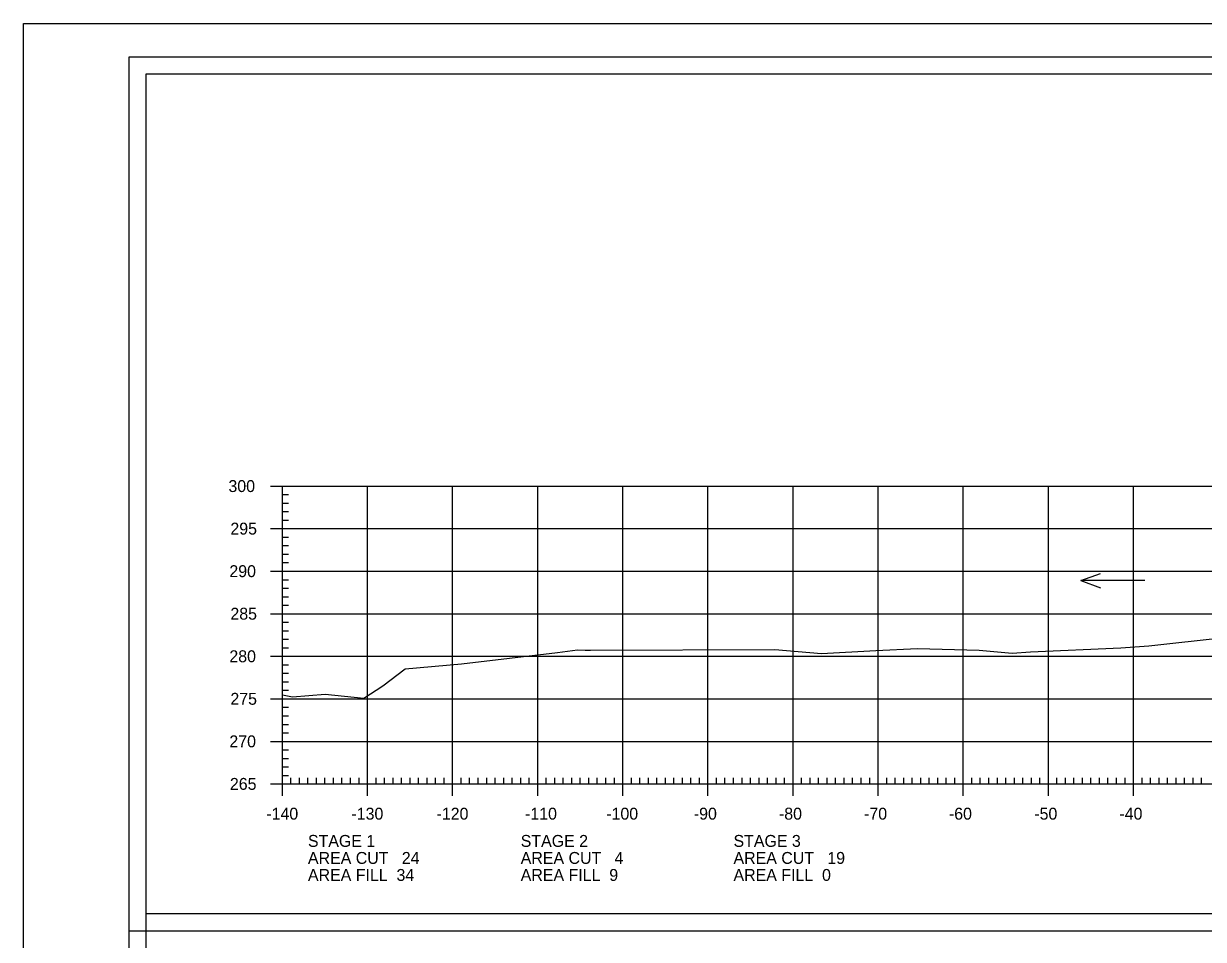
# Model space of a CAD drawing. Extents: x 1368713 to 1370673, y 380279 to 380950.
# Drawn here: x 1370339.2 to 1370477.8, y 380416.1 to 380523.8 of the extents above; entities that cross this region are included whole.
import ezdxf

# ---------------------------------------------------------------- set-up
doc = ezdxf.new("R2010")
doc.units = 0
for name, color, linetype in [('R_Axis', 7, 'Continuous'), ('R_Axis Annot', 7, 'Continuous'), ('R_Border', 7, 'Continuous'), ('R_Border Plan-Plan', 7, 'Continuous'), ('R_Exist Surface', 7, 'Continuous'), ('R_Grid', 7, 'Continuous'), ('R_No Plot', 7, 'Continuous'), ('R_Water Annot', 7, 'Continuous')]:
    doc.layers.add(name, color=color, linetype=linetype)

msp = doc.modelspace()

# ---------------------------------------------------------------- linework, layer by layer
at = {"layer": 'R_Axis'}
for p, q in [((1370368.23, 380469.42), (1370371.03, 380469.42)), ((1370369.63, 380434.42), (1370369.63, 380469.42)), ((1370369.63, 380468.42), (1370370.33, 380468.42)), ((1370369.63, 380467.42), (1370370.33, 380467.42)), ((1370369.63, 380466.42), (1370370.33, 380466.42)), ((1370369.63, 380465.42), (1370370.33, 380465.42)), ((1370368.23, 380464.42), (1370371.03, 380464.42)), ((1370369.63, 380463.42), (1370370.33, 380463.42)), ((1370369.63, 380462.42), (1370370.33, 380462.42)), ((1370369.63, 380461.42), (1370370.33, 380461.42)), ((1370368.23, 380459.42), (1370371.03, 380459.42)), ((1370369.63, 380460.42), (1370370.33, 380460.42)), ((1370369.63, 380458.42), (1370370.33, 380458.42)), ((1370369.63, 380457.42), (1370370.33, 380457.42)), ((1370369.63, 380456.42), (1370370.33, 380456.42)), ((1370369.63, 380455.42), (1370370.33, 380455.42)), ((1370368.23, 380454.42), (1370371.03, 380454.42)), ((1370369.63, 380453.42), (1370370.33, 380453.42)), ((1370369.63, 380452.42), (1370370.33, 380452.42)), ((1370369.63, 380451.42), (1370370.33, 380451.42)), ((1370369.63, 380450.42), (1370370.33, 380450.42)), ((1370368.23, 380449.42), (1370371.03, 380449.42)), ((1370369.63, 380448.42), (1370370.33, 380448.42)), ((1370369.63, 380447.42), (1370370.33, 380447.42)), ((1370369.63, 380446.42), (1370370.33, 380446.42)), ((1370368.23, 380444.42), (1370371.03, 380444.42)), ((1370369.63, 380445.42), (1370370.33, 380445.42)), ((1370369.63, 380443.42), (1370370.33, 380443.42)), ((1370369.63, 380442.42), (1370370.33, 380442.42)), ((1370369.63, 380441.42), (1370370.33, 380441.42)), ((1370369.63, 380440.42), (1370370.33, 380440.42)), ((1370368.23, 380439.42), (1370371.03, 380439.42)), ((1370369.63, 380438.42), (1370370.33, 380438.42)), ((1370369.63, 380437.42), (1370370.33, 380437.42)), ((1370369.63, 380436.42), (1370370.33, 380436.42)), ((1370369.63, 380433.02), (1370369.63, 380435.82)), ((1370379.63, 380433.02), (1370379.63, 380435.82)), ((1370389.63, 380433.02), (1370389.63, 380435.82)), ((1370399.63, 380433.02), (1370399.63, 380435.82)), ((1370409.63, 380433.02), (1370409.63, 380435.82)), ((1370419.63, 380433.02), (1370419.63, 380435.82)), ((1370429.63, 380433.02), (1370429.63, 380435.82)), ((1370439.63, 380433.02), (1370439.63, 380435.82)), ((1370449.63, 380433.02), (1370449.63, 380435.82)), ((1370459.63, 380433.02), (1370459.63, 380435.82)), ((1370469.63, 380433.02), (1370469.63, 380435.82)), ((1370369.63, 380435.42), (1370370.33, 380435.42)), ((1370370.63, 380434.42), (1370370.63, 380435.12)), ((1370371.63, 380434.42), (1370371.63, 380435.12)), ((1370372.63, 380434.42), (1370372.63, 380435.12)), ((1370373.63, 380434.42), (1370373.63, 380435.12)), ((1370374.63, 380434.42), (1370374.63, 380435.12)), ((1370375.63, 380434.42), (1370375.63, 380435.12)), ((1370376.63, 380434.42), (1370376.63, 380435.12)), ((1370377.63, 380434.42), (1370377.63, 380435.12)), ((1370378.63, 380434.42), (1370378.63, 380435.12)), ((1370380.63, 380434.42), (1370380.63, 380435.12)), ((1370381.63, 380434.42), (1370381.63, 380435.12)), ((1370382.63, 380434.42), (1370382.63, 380435.12)), ((1370383.63, 380434.42), (1370383.63, 380435.12)), ((1370384.63, 380434.42), (1370384.63, 380435.12)), ((1370385.63, 380434.42), (1370385.63, 380435.12)), ((1370386.63, 380434.42), (1370386.63, 380435.12)), ((1370387.63, 380434.42), (1370387.63, 380435.12)), ((1370388.63, 380434.42), (1370388.63, 380435.12)), ((1370390.63, 380434.42), (1370390.63, 380435.12)), ((1370391.63, 380434.42), (1370391.63, 380435.12)), ((1370392.63, 380434.42), (1370392.63, 380435.12)), ((1370393.63, 380434.42), (1370393.63, 380435.12)), ((1370394.63, 380434.42), (1370394.63, 380435.12)), ((1370395.63, 380434.42), (1370395.63, 380435.12)), ((1370396.63, 380434.42), (1370396.63, 380435.12)), ((1370397.63, 380434.42), (1370397.63, 380435.12)), ((1370398.63, 380434.42), (1370398.63, 380435.12)), ((1370400.63, 380434.42), (1370400.63, 380435.12)), ((1370401.63, 380434.42), (1370401.63, 380435.12)), ((1370402.63, 380434.42), (1370402.63, 380435.12)), ((1370403.63, 380434.42), (1370403.63, 380435.12)), ((1370404.63, 380434.42), (1370404.63, 380435.12)), ((1370405.63, 380434.42), (1370405.63, 380435.12)), ((1370406.63, 380434.42), (1370406.63, 380435.12)), ((1370407.63, 380434.42), (1370407.63, 380435.12)), ((1370408.63, 380434.42), (1370408.63, 380435.12)), ((1370410.63, 380434.42), (1370410.63, 380435.12)), ((1370411.63, 380434.42), (1370411.63, 380435.12)), ((1370412.63, 380434.42), (1370412.63, 380435.12)), ((1370413.63, 380434.42), (1370413.63, 380435.12)), ((1370414.63, 380434.42), (1370414.63, 380435.12)), ((1370415.63, 380434.42), (1370415.63, 380435.12)), ((1370416.63, 380434.42), (1370416.63, 380435.12)), ((1370417.63, 380434.42), (1370417.63, 380435.12)), ((1370418.63, 380434.42), (1370418.63, 380435.12)), ((1370420.63, 380434.42), (1370420.63, 380435.12)), ((1370421.63, 380434.42), (1370421.63, 380435.12)), ((1370422.63, 380434.42), (1370422.63, 380435.12)), ((1370423.63, 380434.42), (1370423.63, 380435.12)), ((1370424.63, 380434.42), (1370424.63, 380435.12)), ((1370425.63, 380434.42), (1370425.63, 380435.12)), ((1370426.63, 380434.42), (1370426.63, 380435.12)), ((1370427.63, 380434.42), (1370427.63, 380435.12)), ((1370428.63, 380434.42), (1370428.63, 380435.12)), ((1370430.63, 380434.42), (1370430.63, 380435.12)), ((1370431.63, 380434.42), (1370431.63, 380435.12)), ((1370432.63, 380434.42), (1370432.63, 380435.12)), ((1370433.63, 380434.42), (1370433.63, 380435.12)), ((1370434.63, 380434.42), (1370434.63, 380435.12)), ((1370435.63, 380434.42), (1370435.63, 380435.12)), ((1370436.63, 380434.42), (1370436.63, 380435.12)), ((1370437.63, 380434.42), (1370437.63, 380435.12)), ((1370438.63, 380434.42), (1370438.63, 380435.12)), ((1370440.63, 380434.42), (1370440.63, 380435.12)), ((1370441.63, 380434.42), (1370441.63, 380435.12)), ((1370442.63, 380434.42), (1370442.63, 380435.12)), ((1370443.63, 380434.42), (1370443.63, 380435.12)), ((1370444.63, 380434.42), (1370444.63, 380435.12)), ((1370445.63, 380434.42), (1370445.63, 380435.12)), ((1370446.63, 380434.42), (1370446.63, 380435.12)), ((1370447.63, 380434.42), (1370447.63, 380435.12)), ((1370448.63, 380434.42), (1370448.63, 380435.12)), ((1370450.63, 380434.42), (1370450.63, 380435.12)), ((1370451.63, 380434.42), (1370451.63, 380435.12)), ((1370452.63, 380434.42), (1370452.63, 380435.12)), ((1370453.63, 380434.42), (1370453.63, 380435.12)), ((1370454.63, 380434.42), (1370454.63, 380435.12)), ((1370455.63, 380434.42), (1370455.63, 380435.12)), ((1370456.63, 380434.42), (1370456.63, 380435.12)), ((1370457.63, 380434.42), (1370457.63, 380435.12)), ((1370458.63, 380434.42), (1370458.63, 380435.12)), ((1370460.63, 380434.42), (1370460.63, 380435.12)), ((1370461.63, 380434.42), (1370461.63, 380435.12)), ((1370462.63, 380434.42), (1370462.63, 380435.12)), ((1370463.63, 380434.42), (1370463.63, 380435.12)), ((1370464.63, 380434.42), (1370464.63, 380435.12)), ((1370465.63, 380434.42), (1370465.63, 380435.12)), ((1370466.63, 380434.42), (1370466.63, 380435.12)), ((1370467.63, 380434.42), (1370467.63, 380435.12)), ((1370468.63, 380434.42), (1370468.63, 380435.12)), ((1370470.63, 380434.42), (1370470.63, 380435.12)), ((1370471.63, 380434.42), (1370471.63, 380435.12)), ((1370472.63, 380434.42), (1370472.63, 380435.12)), ((1370473.63, 380434.42), (1370473.63, 380435.12)), ((1370474.63, 380434.42), (1370474.63, 380435.12)), ((1370475.63, 380434.42), (1370475.63, 380435.12)), ((1370476.63, 380434.42), (1370476.63, 380435.12)), ((1370477.63, 380434.42), (1370477.63, 380435.12)), ((1370368.23, 380434.42), (1370371.03, 380434.42)), ((1370369.63, 380434.42), (1370649.63, 380434.42))]:
    msp.add_line(p, q, dxfattribs=at)
at = {"layer": 'R_Border'}
for p, q in [((1370351.63, 380519.88), (1370667.81, 380519.88)), ((1370351.63, 380314.42), (1370351.63, 380519.88))]:
    msp.add_line(p, q, dxfattribs=at)
at = {"layer": 'R_Border Plan-Plan'}
msp.add_line((1370351.63, 380417.15), (1370667.81, 380417.15), dxfattribs=at)
at = {"layer": 'R_Exist Surface'}
msp.add_lwpolyline([(1370369.63, 380444.89), (1370370.8, 380444.66), (1370374.64, 380444.98), (1370379.19, 380444.5), (1370381.41, 380445.95), (1370384.06, 380447.93), (1370390.67, 380448.53), (1370401.97, 380449.87), (1370404.31, 380450.16), (1370405.22, 380450.15), (1370405.83, 380450.13), (1370427.5, 380450.23), (1370432.96, 380449.75), (1370439.34, 380450.11), (1370444.26, 380450.35), (1370451.5, 380450.15), (1370455.38, 380449.79), (1370457.51, 380449.94), (1370468.15, 380450.4), (1370471.42, 380450.64), (1370480.29, 380451.63)], dxfattribs=at)
at = {"layer": 'R_Grid'}
for p, q in [((1370369.63, 380469.42), (1370649.63, 380469.42)), ((1370369.63, 380434.42), (1370369.63, 380469.42)), ((1370379.63, 380434.42), (1370379.63, 380469.42)), ((1370389.63, 380434.42), (1370389.63, 380469.42)), ((1370399.63, 380434.42), (1370399.63, 380469.42)), ((1370409.63, 380434.42), (1370409.63, 380469.42)), ((1370419.63, 380434.42), (1370419.63, 380469.42)), ((1370429.63, 380434.42), (1370429.63, 380469.42)), ((1370439.63, 380434.42), (1370439.63, 380469.42)), ((1370449.63, 380434.42), (1370449.63, 380469.42)), ((1370459.63, 380434.42), (1370459.63, 380469.42)), ((1370469.63, 380434.42), (1370469.63, 380469.42)), ((1370369.63, 380464.42), (1370649.63, 380464.42)), ((1370369.63, 380459.42), (1370649.63, 380459.42)), ((1370369.63, 380454.42), (1370649.63, 380454.42)), ((1370369.63, 380449.42), (1370649.63, 380449.42)), ((1370369.63, 380444.42), (1370649.63, 380444.42)), ((1370369.63, 380439.42), (1370649.63, 380439.42)), ((1370369.63, 380434.42), (1370649.63, 380434.42))]:
    msp.add_line(p, q, dxfattribs=at)
at = {"layer": 'R_No Plot'}
for points in [[(1370339.22, 380523.77), (1370672.56, 380523.77), (1370672.56, 380310.43), (1370339.22, 380310.43)], [(1370665.81, 380419.15), (1370353.63, 380419.15), (1370353.63, 380517.88), (1370603.17, 380517.88), (1370603.17, 380508), (1370620.71, 380508), (1370644.81, 380508), (1370644.81, 380485.66), (1370665.81, 380485.66)], [(1370353.63, 380517.88), (1370603.17, 380517.88), (1370603.17, 380508), (1370620.71, 380508), (1370644.81, 380508), (1370644.81, 380485.66), (1370665.81, 380485.66), (1370665.81, 380316.42), (1370353.63, 380316.42)]]:
    msp.add_lwpolyline(points, close=True, dxfattribs=at)
at = {"layer": 'R_Water Annot'}
for p, q in [((1370463.43, 380458.31), (1370465.74, 380459.15)), ((1370470.97, 380458.31), (1370463.43, 380458.31)), ((1370463.43, 380458.31), (1370465.74, 380457.47))]:
    msp.add_line(p, q, dxfattribs=at)

# ---------------------------------------------------------------- texts
at = {"layer": 'R_Axis Annot'}
for s, p in [('300', (1370363.29, 380468.72)), ('295', (1370363.52, 380463.72)), ('290', (1370363.4, 380458.72)), ('285', (1370363.52, 380453.72)), ('280', (1370363.4, 380448.72)), ('275', (1370363.52, 380443.72)), ('270', (1370363.4, 380438.72)), ('265', (1370363.46, 380433.72)), ('-140', (1370367.74, 380430.22)), ('-130', (1370377.74, 380430.22)), ('-120', (1370387.74, 380430.22)), ('-110', (1370398.14, 380430.22)), ('-100', (1370407.68, 380430.22)), ('-90', (1370417.97, 380430.22)), ('-80', (1370427.97, 380430.22)), ('-70', (1370437.97, 380430.22)), ('-60', (1370447.94, 380430.22)), ('-50', (1370457.97, 380430.22)), ('-40', (1370467.97, 380430.22)), ('STAGE 1', (1370372.63, 380427.02)), ('STAGE 2', (1370397.63, 380427.02)), ('STAGE 3', (1370422.63, 380427.02)), ('AREA CUT   24', (1370372.63, 380425.02)), ('AREA CUT   4', (1370397.63, 380425.02)), ('AREA CUT   19', (1370422.63, 380425.02)), ('AREA FILL  34', (1370372.63, 380423.02)), ('AREA FILL  9', (1370397.63, 380423.02)), ('AREA FILL  0', (1370422.63, 380423.02))]:
    msp.add_text(s, height=1.4, dxfattribs=at).set_placement(p)

doc.saveas('drawing.dxf')
